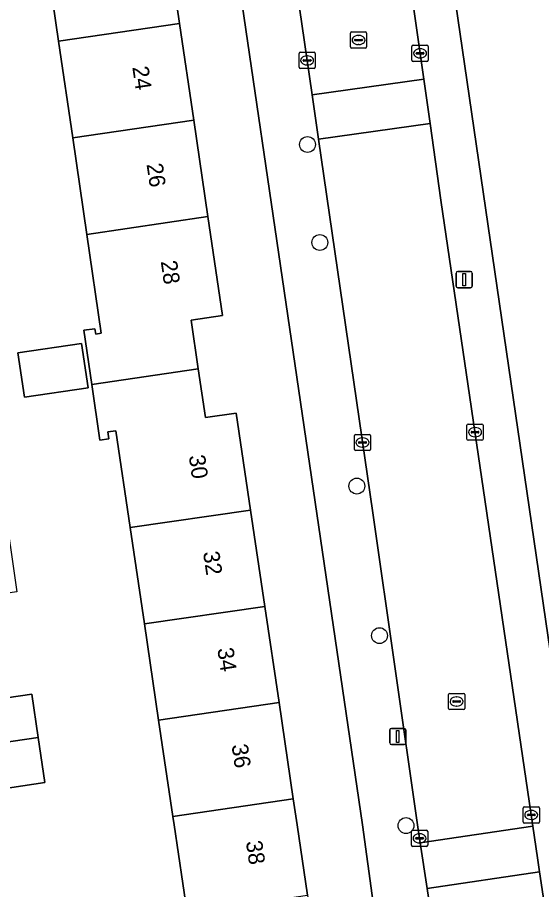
# Model space of a CAD drawing. Extents: x 159053 to 160042, y 380449 to 381423.
# Drawn here: x 159364.5 to 159396.8, y 380996 to 381049.8 of the extents above; entities that cross this region are included whole.
import ezdxf

# ---------------------------------------------------------------- set-up
doc = ezdxf.new("R2010")
doc.units = 0
for name, color, linetype in [('IMGEO_Boom', 7, 'Continuous'), ('IMGEO_Erf', 7, 'Continuous'), ('IMGEO_Kolk', 7, 'Continuous'), ('IMGEO_Lichtmast', 7, 'Continuous'), ('IMGEO_Pand', 7, 'Continuous'), ('IMGEO_Pand_nummerreeks', 7, 'Continuous'), ('IMGEO_Rijbaan_lokaal_open', 7, 'Continuous'), ('IMGEO_Rioolput', 7, 'Continuous'), ('IMGEO_Voetpad_open', 7, 'Continuous')]:
    doc.layers.add(name, color=color, linetype=linetype)

msp = doc.modelspace()

# ---------------------------------------------------------------- linework, layer by layer
at = {"layer": 'IMGEO_Boom'}
for centre in [(159382.372, 381041.927), (159383.129, 381035.889), (159385.41, 381020.873), (159386.808, 381011.654), (159388.442, 380999.945)]:
    msp.add_circle(centre, 0.489, dxfattribs=at)
at = {"layer": 'IMGEO_Erf'}
for points in [[(159373.62, 381055.349), (159374.491, 381049.393), (159375.363, 381043.436), (159376.234, 381037.479), (159377.126, 381031.385), (159375.2, 381031.103), (159375.639, 381028.098), (159376.079, 381025.09), (159377.975, 381025.368), (159378.859, 381019.396), (159379.737, 381013.46), (159380.615, 381007.525), (159381.494, 381001.59), (159381.729, 381000), (159382.372, 380995.654), (159383.25, 380989.719), (159384.129, 380983.783), (159385.012, 380977.812), (159388.726, 380978.358), (159385.752, 381000), (159373.296, 381085.027)], [(159386.52, 381084.815), (159398.888, 381000), (159401.289, 380983.538), (159407.214, 380984.584), (159406.316, 380990.699), (159405.443, 380996.635), (159404.949, 381000), (159404.571, 381002.571), (159403.699, 381008.508), (159402.826, 381014.444), (159401.954, 381020.38), (159401.055, 381026.497), (159402.8, 381026.752), (159402.368, 381029.705), (159401.936, 381032.662), (159400.109, 381032.395), (159399.195, 381038.639)], [(159374.948, 380994.574), (159374.146, 381000), (159374.071, 381000.51), (159373.193, 381006.445), (159372.316, 381012.38), (159371.439, 381018.316), (159370.557, 381024.282), (159370.063, 381024.21), (159370.136, 381023.775), (159369.575, 381023.705), (159369.072, 381027.137), (159368.584, 381030.473), (159369.254, 381030.562), (159369.316, 381030.242), (159369.661, 381030.292), (159368.769, 381036.388), (159367.898, 381042.344), (159367.026, 381048.302), (159366.155, 381054.257)], [(159355.054, 381049.806), (159355.997, 381043.355), (159360.084, 381043.953), (159360.479, 381041.259), (159360.884, 381038.491), (159356.797, 381037.893), (159357.651, 381032.154), (159361.445, 381032.719), (159362.433, 381026.084), (159358.638, 381025.52), (159359.575, 381019.226), (159363.662, 381019.824), (159364.062, 381017.095), (159364.462, 381014.362), (159360.375, 381013.764), (159361.292, 381007.456), (159365.379, 381008.054), (159365.773, 381005.365), (159366.179, 381002.592), (159362.092, 381001.994), (159362.878, 380995.342)]]:
    msp.add_lwpolyline(points, dxfattribs=at)
msp.add_lwpolyline([(159364.525, 381029.082), (159368.449, 381029.657), (159368.849, 381026.931), (159364.924, 381026.356)], close=True, dxfattribs=at)
at = {"layer": 'IMGEO_Kolk'}
for p, q in [((159388.807, 381047.121), (159388.807, 381047.973)), ((159388.882, 381048.047), (159389.734, 381048.047)), ((159389.295, 381047.827), (159389.32, 381047.827)), ((159389.808, 381047.973), (159389.808, 381047.121)), ((159381.847, 381046.684), (159381.847, 381047.536)), ((159381.922, 381047.61), (159382.774, 381047.61)), ((159382.335, 381047.39), (159382.36, 381047.39)), ((159382.848, 381047.536), (159382.848, 381046.684)), ((159389.066, 381047.541), (159389.066, 381047.553)), ((159389.504, 381047.504), (159389.106, 381047.504)), ((159389.109, 381047.59), (159389.507, 381047.59)), ((159389.318, 381047.267), (159389.293, 381047.267)), ((159389.55, 381047.553), (159389.55, 381047.541)), ((159382.106, 381047.104), (159382.106, 381047.116)), ((159382.544, 381047.067), (159382.146, 381047.067)), ((159382.149, 381047.153), (159382.547, 381047.153)), ((159382.358, 381046.83), (159382.333, 381046.83)), ((159382.59, 381047.116), (159382.59, 381047.104)), ((159389.734, 381047.047), (159388.882, 381047.047)), ((159382.774, 381046.61), (159381.922, 381046.61)), ((159392.271, 381024.697), (159393.123, 381024.697)), ((159392.196, 381023.771), (159392.196, 381024.623)), ((159392.455, 381024.191), (159392.455, 381024.203)), ((159392.893, 381024.154), (159392.495, 381024.154)), ((159392.498, 381024.24), (159392.896, 381024.24)), ((159392.684, 381024.477), (159392.709, 381024.477)), ((159392.939, 381024.203), (159392.939, 381024.191)), ((159393.197, 381024.623), (159393.197, 381023.771)), ((159385.259, 381023.132), (159385.259, 381023.984)), ((159385.334, 381024.058), (159386.186, 381024.058)), ((159385.747, 381023.838), (159385.772, 381023.838)), ((159386.26, 381023.984), (159386.26, 381023.132)), ((159393.123, 381023.697), (159392.271, 381023.697)), ((159392.707, 381023.917), (159392.682, 381023.917)), ((159385.518, 381023.552), (159385.518, 381023.564)), ((159385.956, 381023.515), (159385.558, 381023.515)), ((159385.561, 381023.601), (159385.959, 381023.601)), ((159385.77, 381023.278), (159385.745, 381023.278)), ((159386.002, 381023.564), (159386.002, 381023.552)), ((159386.186, 381023.058), (159385.334, 381023.058)), ((159395.736, 381001.101), (159396.588, 381001.101)), ((159395.661, 381000.175), (159395.661, 381001.027)), ((159395.92, 381000.595), (159395.92, 381000.607)), ((159396.358, 381000.558), (159395.96, 381000.558)), ((159395.963, 381000.644), (159396.361, 381000.644)), ((159396.149, 381000.881), (159396.174, 381000.881)), ((159396.404, 381000.607), (159396.404, 381000.595)), ((159396.662, 381001.027), (159396.662, 381000.175)), ((159396.588, 381000.101), (159395.736, 381000.101)), ((159396.172, 381000.321), (159396.147, 381000.321)), ((159388.776, 380998.735), (159388.776, 380999.587)), ((159388.851, 380999.661), (159389.703, 380999.661)), ((159389.264, 380999.441), (159389.289, 380999.441)), ((159389.777, 380999.587), (159389.777, 380998.735)), ((159389.035, 380999.155), (159389.035, 380999.167)), ((159389.473, 380999.118), (159389.075, 380999.118)), ((159389.078, 380999.204), (159389.476, 380999.204)), ((159389.287, 380998.881), (159389.262, 380998.881)), ((159389.519, 380999.167), (159389.519, 380999.155)), ((159389.703, 380998.661), (159388.851, 380998.661))]:
    msp.add_line(p, q, dxfattribs=at)
for points in [[(159388.807, 381047.121), (159388.807, 381047.973)], [(159388.882, 381048.047), (159389.734, 381048.047)], [(159389.808, 381047.973), (159389.808, 381047.121)], [(159381.847, 381046.684), (159381.847, 381047.536)], [(159381.922, 381047.61), (159382.774, 381047.61)], [(159382.848, 381047.536), (159382.848, 381046.684)], [(159389.734, 381047.047), (159388.882, 381047.047)], [(159382.774, 381046.61), (159381.922, 381046.61)], [(159392.271, 381024.697), (159393.123, 381024.697)], [(159392.196, 381023.771), (159392.196, 381024.623)], [(159393.197, 381024.623), (159393.197, 381023.771)], [(159385.259, 381023.132), (159385.259, 381023.984)], [(159385.334, 381024.058), (159386.186, 381024.058)], [(159386.26, 381023.984), (159386.26, 381023.132)], [(159393.123, 381023.697), (159392.271, 381023.697)], [(159386.186, 381023.058), (159385.334, 381023.058)], [(159395.736, 381001.101), (159396.588, 381001.101)], [(159395.661, 381000.175), (159395.661, 381001.027)], [(159396.662, 381001.027), (159396.662, 381000.175)], [(159396.588, 381000.101), (159395.736, 381000.101)], [(159388.776, 380998.735), (159388.776, 380999.587)], [(159388.851, 380999.661), (159389.703, 380999.661)], [(159389.777, 380999.587), (159389.777, 380998.735)], [(159389.703, 380998.661), (159388.851, 380998.661)]]:
    msp.add_lwpolyline(points, dxfattribs=at)
for centre, radius, start, end in [((159388.884, 381047.971), 0.0765, 91.552, 178.448), ((159388.884, 381047.971), 0.0765, 91.552, 178.448), ((159389.732, 381047.971), 0.0765, 1.552, 88.448), ((159389.732, 381047.971), 0.0765, 1.552, 88.448), ((159381.924, 381047.534), 0.0765, 91.552, 178.448), ((159381.924, 381047.534), 0.0765, 91.552, 178.448), ((159382.772, 381047.534), 0.0765, 1.552, 88.448), ((159382.772, 381047.534), 0.0765, 1.552, 88.448), ((159389.106, 381047.55), 0.0403, 85.8775, 175.7526), ((159389.103, 381047.54), 0.0366, 178.938, 274.7102), ((159389.507, 381047.547), 0.043, 264.8664, 352.4533), ((159389.511, 381047.552), 0.0386, 1.7309, 96.639), ((159382.146, 381047.113), 0.0403, 85.8775, 175.7526), ((159382.143, 381047.103), 0.0366, 178.938, 274.7102), ((159382.547, 381047.11), 0.043, 264.8664, 352.4533), ((159382.551, 381047.115), 0.0386, 1.7309, 96.639), ((159388.884, 381047.123), 0.0765, 181.552, 268.448), ((159388.884, 381047.123), 0.0765, 181.552, 268.448), ((159389.732, 381047.123), 0.0765, 271.552, 358.448), ((159389.732, 381047.123), 0.0765, 271.552, 358.448), ((159381.924, 381046.686), 0.0765, 181.552, 268.448), ((159381.924, 381046.686), 0.0765, 181.552, 268.448), ((159382.772, 381046.686), 0.0765, 271.552, 358.448), ((159382.772, 381046.686), 0.0765, 271.552, 358.448), ((159392.273, 381024.621), 0.0765, 91.552, 178.448), ((159392.273, 381024.621), 0.0765, 91.552, 178.448), ((159393.121, 381024.621), 0.0765, 1.552, 88.448), ((159393.121, 381024.621), 0.0765, 1.552, 88.448), ((159392.495, 381024.2), 0.0403, 85.8775, 175.7526), ((159392.492, 381024.19), 0.0366, 178.938, 274.7102), ((159392.896, 381024.197), 0.043, 264.8664, 352.4533), ((159392.9, 381024.202), 0.0386, 1.7309, 96.639), ((159385.336, 381023.982), 0.0765, 91.552, 178.448), ((159385.336, 381023.982), 0.0765, 91.552, 178.448), ((159386.184, 381023.982), 0.0765, 1.552, 88.448), ((159386.184, 381023.982), 0.0765, 1.552, 88.448), ((159392.273, 381023.773), 0.0765, 181.552, 268.448), ((159392.273, 381023.773), 0.0765, 181.552, 268.448), ((159393.121, 381023.773), 0.0765, 271.552, 358.448), ((159393.121, 381023.773), 0.0765, 271.552, 358.448), ((159385.336, 381023.134), 0.0765, 181.552, 268.448), ((159385.336, 381023.134), 0.0765, 181.552, 268.448), ((159385.558, 381023.561), 0.0403, 85.8775, 175.7526), ((159385.555, 381023.551), 0.0366, 178.938, 274.7102), ((159385.959, 381023.558), 0.043, 264.8664, 352.4533), ((159385.963, 381023.563), 0.0386, 1.7309, 96.639), ((159386.184, 381023.134), 0.0765, 271.552, 358.448), ((159386.184, 381023.134), 0.0765, 271.552, 358.448), ((159395.738, 381001.025), 0.0765, 91.552, 178.448), ((159395.738, 381001.025), 0.0765, 91.552, 178.448), ((159396.586, 381001.025), 0.0765, 1.552, 88.448), ((159396.586, 381001.025), 0.0765, 1.552, 88.448), ((159395.96, 381000.604), 0.0403, 85.8775, 175.7526), ((159395.957, 381000.594), 0.0366, 178.938, 274.7102), ((159396.361, 381000.601), 0.043, 264.8664, 352.4533), ((159396.365, 381000.606), 0.0386, 1.7309, 96.639), ((159395.738, 381000.177), 0.0765, 181.552, 268.448), ((159395.738, 381000.177), 0.0765, 181.552, 268.448), ((159396.586, 381000.177), 0.0765, 271.552, 358.448), ((159396.586, 381000.177), 0.0765, 271.552, 358.448), ((159388.853, 380999.585), 0.0765, 91.552, 178.448), ((159388.853, 380999.585), 0.0765, 91.552, 178.448), ((159389.701, 380999.585), 0.0765, 1.552, 88.448), ((159389.701, 380999.585), 0.0765, 1.552, 88.448), ((159389.075, 380999.164), 0.0403, 85.8775, 175.7526), ((159389.072, 380999.154), 0.0366, 178.938, 274.7102), ((159389.476, 380999.161), 0.043, 264.8664, 352.4533), ((159389.48, 380999.166), 0.0386, 1.7309, 96.639), ((159388.853, 380998.737), 0.0765, 181.552, 268.448), ((159388.853, 380998.737), 0.0765, 181.552, 268.448), ((159389.701, 380998.737), 0.0765, 271.552, 358.448), ((159389.701, 380998.737), 0.0765, 271.552, 358.448)]:
    msp.add_arc(centre, radius, start, end, dxfattribs=at)
for centre, major_axis, ratio, start_param, end_param in [((159389.294, 381047.547), (-0.387, 0.002), 0.722429, 4.712389, 7.853982), ((159389.319, 381047.547), (-0.39, 0.002), 0.717154, 1.570796, 4.712389), ((159382.334, 381047.11), (-0.387, 0.002), 0.722429, 4.712389, 7.853982), ((159382.359, 381047.11), (-0.39, 0.002), 0.717154, 1.570796, 4.712389), ((159392.683, 381024.197), (-0.387, 0.002), 0.722429, 4.712389, 7.853982), ((159392.708, 381024.197), (-0.39, 0.002), 0.717154, 1.570796, 4.712389), ((159385.746, 381023.558), (-0.387, 0.002), 0.722429, 4.712389, 7.853982), ((159385.771, 381023.558), (-0.39, 0.002), 0.717154, 1.570796, 4.712389), ((159396.148, 381000.601), (-0.387, 0.002), 0.722429, 4.712389, 7.853982), ((159396.173, 381000.601), (-0.39, 0.002), 0.717154, 1.570796, 4.712389), ((159389.263, 380999.161), (-0.387, 0.002), 0.722429, 4.712389, 7.853982), ((159389.288, 380999.161), (-0.39, 0.002), 0.717154, 1.570796, 4.712389)]:
    msp.add_ellipse(centre, major_axis=major_axis, ratio=ratio, start_param=start_param, end_param=end_param, dxfattribs=at)
at = {"layer": 'IMGEO_Lichtmast'}
for p, q in [((159391.532, 381033.198), (159391.532, 381033.998)), ((159391.532, 381033.998), (159391.532, 381033.198)), ((159391.632, 381034.098), (159392.422, 381034.098)), ((159392.422, 381034.098), (159391.632, 381034.098)), ((159392.522, 381033.998), (159392.522, 381033.198)), ((159392.522, 381033.198), (159392.522, 381033.998)), ((159392.422, 381033.098), (159391.632, 381033.098)), ((159391.632, 381033.098), (159392.422, 381033.098)), ((159387.537, 381005.94), (159388.327, 381005.94)), ((159388.327, 381005.94), (159387.537, 381005.94)), ((159387.437, 381005.04), (159387.437, 381005.84)), ((159387.437, 381005.84), (159387.437, 381005.04)), ((159388.427, 381005.84), (159388.427, 381005.04)), ((159388.427, 381005.04), (159388.427, 381005.84)), ((159388.327, 381004.94), (159387.537, 381004.94)), ((159387.537, 381004.94), (159388.327, 381004.94))]:
    msp.add_line(p, q, dxfattribs=at)
for points in [[(159391.952, 381033.973), (159392.102, 381033.973), (159392.102, 381033.223), (159391.952, 381033.223), (159391.952, 381033.973)], [(159387.857, 381005.815), (159388.007, 381005.815), (159388.007, 381005.065), (159387.857, 381005.065), (159387.857, 381005.815)]]:
    msp.add_lwpolyline(points, dxfattribs=at)
for centre, start, end in [((159391.632, 381033.998), 90, 180), ((159391.632, 381033.998), 90, 180), ((159392.422, 381033.998), 0, 90), ((159392.422, 381033.998), 360, 90), ((159391.632, 381033.198), 180, 270), ((159391.632, 381033.198), 180, 270), ((159392.422, 381033.198), 270, 0), ((159392.422, 381033.198), 270, 0), ((159387.537, 381005.84), 90, 180), ((159387.537, 381005.84), 90, 180), ((159388.327, 381005.84), 0, 90), ((159388.327, 381005.84), 360, 90), ((159387.537, 381005.04), 180, 270), ((159387.537, 381005.04), 180, 270), ((159388.327, 381005.04), 270, 0), ((159388.327, 381005.04), 270, 0)]:
    msp.add_arc(centre, 0.1, start, end, dxfattribs=at)
at = {"layer": 'IMGEO_Pand'}
for points in [[(159367.026, 381048.302), (159374.491, 381049.393), (159373.62, 381055.349), (159366.155, 381054.257)], [(159367.898, 381042.344), (159375.363, 381043.436), (159374.491, 381049.393), (159367.026, 381048.302)], [(159367.898, 381042.344), (159368.769, 381036.388), (159376.234, 381037.479), (159375.363, 381043.436)], [(159375.639, 381028.098), (159375.2, 381031.103), (159377.126, 381031.385), (159376.234, 381037.479), (159368.769, 381036.388), (159369.661, 381030.292), (159369.316, 381030.242), (159369.254, 381030.562), (159368.584, 381030.473), (159369.072, 381027.137)], [(159364.525, 381029.082), (159364.924, 381026.356), (159368.849, 381026.931), (159368.449, 381029.657)], [(159375.639, 381028.098), (159369.072, 381027.137), (159369.575, 381023.705), (159370.136, 381023.775), (159370.063, 381024.21), (159370.557, 381024.282), (159371.439, 381018.316), (159378.859, 381019.396), (159377.975, 381025.368), (159376.079, 381025.09)], [(159379.737, 381013.46), (159378.859, 381019.396), (159371.439, 381018.316), (159372.316, 381012.38)], [(159373.193, 381006.445), (159380.615, 381007.525), (159379.737, 381013.46), (159372.316, 381012.38)], [(159361.685, 381004.77), (159365.773, 381005.365), (159365.379, 381008.054), (159361.292, 381007.456)], [(159373.193, 381006.445), (159374.071, 381000.51), (159381.494, 381001.59), (159380.615, 381007.525)], [(159361.685, 381004.77), (159362.092, 381001.994), (159366.179, 381002.592), (159365.773, 381005.365)], [(159374.948, 380994.574), (159382.372, 380995.654), (159381.729, 381000), (159381.494, 381001.59), (159374.071, 381000.51), (159374.146, 381000)]]:
    msp.add_lwpolyline(points, close=True, dxfattribs=at)
at = {"layer": 'IMGEO_Rijbaan_lokaal_open'}
for points in [[(159382.658, 381044.981), (159389.532, 381045.961), (159385.799, 381072.168), (159383.303, 381088.805), (159382.253, 381096.095), (159375.359, 381095.076), (159380.323, 381061.093)], [(159382.658, 381044.981), (159383.053, 381042.25), (159389.922, 381043.228), (159389.532, 381045.961)], [(159383.053, 381042.25), (159386.389, 381019.228), (159389.147, 381000), (159389.315, 380998.881), (159396.262, 380999.919), (159390.597, 381038.488), (159389.922, 381043.228)], [(159396.672, 380997.098), (159396.542, 380997.966), (159396.262, 380999.919), (159389.315, 380998.881), (159389.737, 380996.062)]]:
    msp.add_lwpolyline(points, close=True, dxfattribs=at)
msp.add_lwpolyline([(159399.81, 380976.439), (159399.691, 380976.895), (159399.477, 380978.287), (159399.423, 380978.652), (159398.743, 380983.277), (159396.672, 380997.098), (159389.737, 380996.062), (159392.402, 380978.279), (159392.726, 380976.187), (159393.059, 380974.243)], dxfattribs=at)
at = {"layer": 'IMGEO_Rioolput'}
for p, q in [((159385.015, 381047.94), (159385.015, 381048.792)), ((159385.09, 381048.866), (159385.942, 381048.866)), ((159385.274, 381048.36), (159385.274, 381048.372)), ((159385.317, 381048.409), (159385.715, 381048.409)), ((159385.503, 381048.646), (159385.528, 381048.646)), ((159385.758, 381048.372), (159385.758, 381048.36)), ((159386.016, 381048.792), (159386.016, 381047.94)), ((159385.942, 381047.866), (159385.09, 381047.866)), ((159385.712, 381048.323), (159385.314, 381048.323)), ((159385.526, 381048.086), (159385.501, 381048.086)), ((159391.06, 381007.167), (159391.06, 381008.019)), ((159391.135, 381008.093), (159391.987, 381008.093)), ((159392.061, 381008.019), (159392.061, 381007.167)), ((159391.319, 381007.587), (159391.319, 381007.599)), ((159391.757, 381007.55), (159391.359, 381007.55)), ((159391.362, 381007.636), (159391.76, 381007.636)), ((159391.548, 381007.873), (159391.573, 381007.873)), ((159391.803, 381007.599), (159391.803, 381007.587)), ((159391.987, 381007.093), (159391.135, 381007.093)), ((159391.571, 381007.313), (159391.546, 381007.313))]:
    msp.add_line(p, q, dxfattribs=at)
for points in [[(159385.015, 381047.94), (159385.015, 381048.792)], [(159385.09, 381048.866), (159385.942, 381048.866)], [(159386.016, 381048.792), (159386.016, 381047.94)], [(159385.942, 381047.866), (159385.09, 381047.866)], [(159391.06, 381007.167), (159391.06, 381008.019)], [(159391.135, 381008.093), (159391.987, 381008.093)], [(159392.061, 381008.019), (159392.061, 381007.167)], [(159391.987, 381007.093), (159391.135, 381007.093)]]:
    msp.add_lwpolyline(points, dxfattribs=at)
for centre, radius, start, end in [((159385.092, 381048.79), 0.0765, 91.552, 178.448), ((159385.092, 381048.79), 0.0765, 91.552, 178.448), ((159385.314, 381048.369), 0.0403, 85.8775, 175.7526), ((159385.311, 381048.359), 0.0366, 178.938, 274.7102), ((159385.715, 381048.366), 0.043, 264.8664, 352.4533), ((159385.719, 381048.371), 0.0386, 1.7309, 96.639), ((159385.94, 381048.79), 0.0765, 1.552, 88.448), ((159385.94, 381048.79), 0.0765, 1.552, 88.448), ((159385.092, 381047.942), 0.0765, 181.552, 268.448), ((159385.092, 381047.942), 0.0765, 181.552, 268.448), ((159385.94, 381047.942), 0.0765, 271.552, 358.448), ((159385.94, 381047.942), 0.0765, 271.552, 358.448), ((159391.137, 381008.017), 0.0765, 91.552, 178.448), ((159391.137, 381008.017), 0.0765, 91.552, 178.448), ((159391.985, 381008.017), 0.0765, 1.552, 88.448), ((159391.985, 381008.017), 0.0765, 1.552, 88.448), ((159391.359, 381007.596), 0.0403, 85.8775, 175.7526), ((159391.356, 381007.586), 0.0366, 178.938, 274.7102), ((159391.76, 381007.593), 0.043, 264.8664, 352.4533), ((159391.764, 381007.598), 0.0386, 1.7309, 96.639), ((159391.137, 381007.169), 0.0765, 181.552, 268.448), ((159391.137, 381007.169), 0.0765, 181.552, 268.448), ((159391.985, 381007.169), 0.0765, 271.552, 358.448), ((159391.985, 381007.169), 0.0765, 271.552, 358.448)]:
    msp.add_arc(centre, radius, start, end, dxfattribs=at)
for centre, major_axis, ratio, start_param, end_param in [((159385.502, 381048.366), (-0.387, 0.002), 0.722429, 4.712389, 7.853982), ((159385.527, 381048.366), (-0.39, 0.002), 0.717154, 1.570796, 4.712389), ((159391.547, 381007.593), (-0.387, 0.002), 0.722429, 4.712389, 7.853982), ((159391.572, 381007.593), (-0.39, 0.002), 0.717154, 1.570796, 4.712389)]:
    msp.add_ellipse(centre, major_axis=major_axis, ratio=ratio, start_param=start_param, end_param=end_param, dxfattribs=at)
at = {"layer": 'IMGEO_Voetpad_open'}
for points in [[(159371.251, 381120.987), (159368.043, 381121.201), (159372.107, 381092.995), (159372.706, 381088.84), (159373.296, 381085.027), (159385.752, 381000), (159388.726, 380978.358), (159388.759, 380977.514)], [(159379.085, 381116.801), (159379.229, 381115.714), (159381.855, 381098.856), (159382.253, 381096.095), (159383.303, 381088.805), (159385.799, 381072.168), (159389.532, 381045.961), (159389.922, 381043.228), (159390.597, 381038.488), (159396.262, 380999.919), (159396.542, 380997.966), (159396.672, 380997.098), (159398.743, 380983.277), (159399.423, 380978.652), (159405.022, 380980.072)], [(159387.185, 380974.856), (159392.726, 380976.187), (159392.402, 380978.279), (159389.737, 380996.062), (159389.315, 380998.881), (159389.147, 381000), (159386.389, 381019.228), (159383.053, 381042.25), (159382.658, 381044.981), (159380.323, 381061.093), (159375.359, 381095.076)], [(159398.888, 381000), (159386.52, 381084.815)]]:
    msp.add_lwpolyline(points, dxfattribs=at)

# ---------------------------------------------------------------- texts
at = {"layer": 'IMGEO_Pand_nummerreeks'}
for s, rotation, p in [('24', 278.3243, (159371.571, 381046.696)), ('26', 278.3243, (159372.447, 381040.709)), ('28', 278.3243, (159373.323, 381034.719)), ('30', 278.4175, (159375.05, 381022.731)), ('32', 278.4175, (159375.928, 381016.794)), ('34', 278.4175, (159376.808, 381010.849)), ('36', 278.4175, (159377.687, 381004.906)), ('38', 278.4166, (159378.569, 380998.952))]:
    msp.add_text(s, height=1, rotation=rotation, dxfattribs=at).set_placement(p)

doc.saveas('drawing.dxf')
